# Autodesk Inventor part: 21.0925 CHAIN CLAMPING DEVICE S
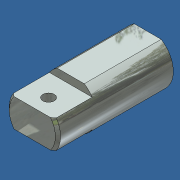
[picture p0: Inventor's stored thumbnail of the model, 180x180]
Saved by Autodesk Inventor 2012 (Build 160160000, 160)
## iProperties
Created: 2012-06
Part Number: 21.0925 CHAIN CLAMPING DEVICE S
Document SubType Name: Modeling
Designer: Administrator
Density: 7.85 g/cm^3
Material: Steel
Mass: 79.9264 g
Surface Area: 43.1751 cm^2
Volume: 10.1817 cm^3
Author: Administrator
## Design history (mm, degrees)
feature "Base1"
body "Solid1"
